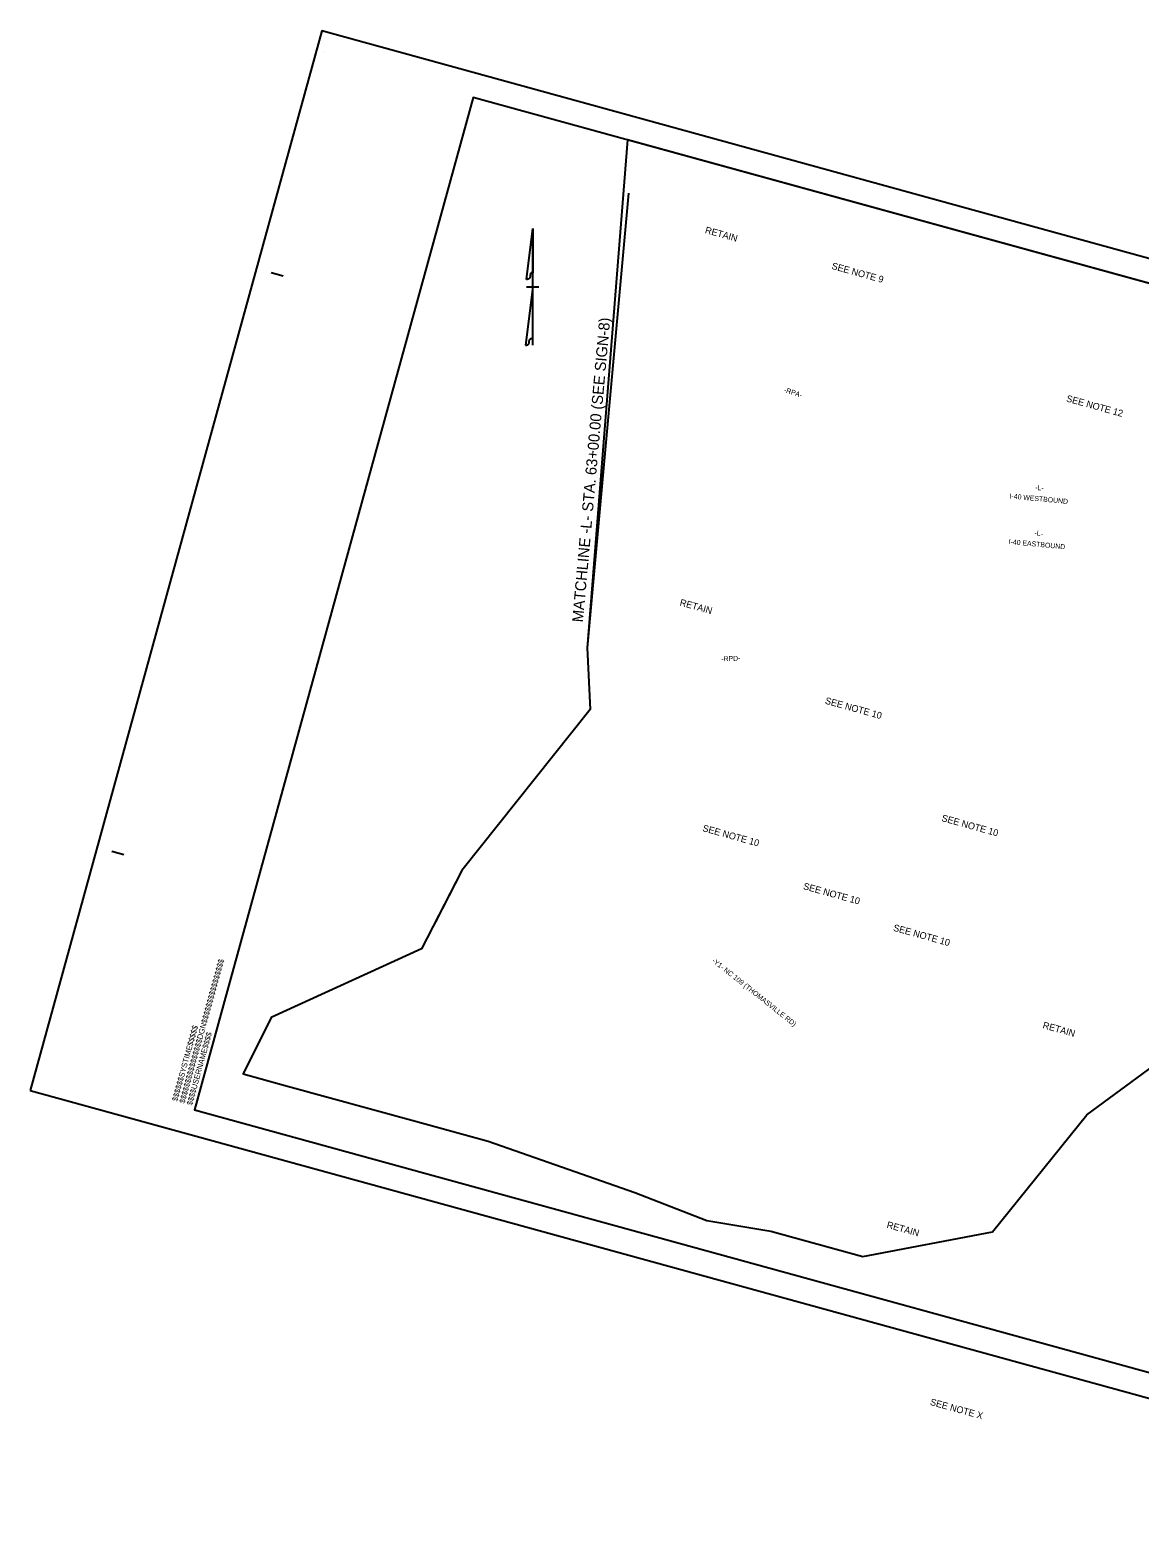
# Model space of a CAD drawing. Extents: x 1641195 to 1643343, y 841291 to 842800.
# Drawn here: x 1641195 to 1642306, y 841291 to 842800 of the extents above; entities that cross this region are included whole.
import ezdxf

# ---------------------------------------------------------------- set-up
doc = ezdxf.new("R2010")
doc.units = 0
for name, color, linetype in [('Default', 7, 'Continuous'), ('Level 14', 7, 'Continuous'), ('Level 15', 7, 'Continuous'), ('Level 17', 7, 'Continuous'), ('Level 2', 7, 'Continuous'), ('Level 3', 7, 'Continuous'), ('Level 5', 7, 'Continuous'), ('Level 6', 7, 'Continuous')]:
    doc.layers.add(name, color=color, linetype=linetype)

msp = doc.modelspace()

# ---------------------------------------------------------------- linework, layer by layer
at = {"layer": 'Level 14'}
msp.add_lwpolyline([(1641793.8, 842636.9), (1641752.4, 842181.8), (1641755.5, 842119.8), (1641627.2, 841958.8), (1641600.7, 841907.5)], dxfattribs=at)
at = {"layer": 'Level 15'}
for p, q in [((1641691.8, 842550.5), (1641698, 842601.5)), ((1641691.8, 842550.5), (1641698, 842601.5)), ((1641698, 842484.7), (1641698, 842601.5)), ((1641698, 842601.5), (1641698, 842557.2)), ((1641698, 842601.5), (1641698, 842557.2)), ((1641698, 842543.1), (1641690.8, 842484.7)), ((1641691.8, 842543.1), (1641704.3, 842543.1)), ((1641698, 842491.6), (1641698, 842543.1))]:
    msp.add_line(p, q, dxfattribs=at)
for points in [[(1641698, 842557.2), (1641695.5, 842557.5), (1641695.4, 842550.4), (1641691.8, 842550.5)], [(1641698, 842557.2), (1641695.5, 842557.5), (1641695.4, 842550.4), (1641691.8, 842550.5)], [(1641690.8, 842484.7), (1641694.5, 842484.5), (1641694.6, 842491.6), (1641698, 842491.6)]]:
    msp.add_open_spline(points, degree=2, dxfattribs=at)
at = {"layer": 'Level 2'}
msp.add_lwpolyline([(1641195.1, 841738.6), (1642822.6, 841290.7), (1643114.4, 842351.3), (1641486.9, 842799.2)], close=True, dxfattribs=at)
at = {"layer": 'Level 3'}
for p, q in [((1641488, 842800), (1641488, 842800)), ((1641489.6, 842777.7), (1641489.6, 842777.7)), ((1641639.4, 842732.4), (1641639.4, 842732.4)), ((1641436.2, 842557.3), (1641448.3, 842554)), ((1641276.9, 841978.2), (1641288.9, 841974.9)), ((1641359.5, 841719.2), (1641359.5, 841719.2)), ((1641359.5, 841719.2), (1641359.5, 841719.2)), ((1641359.5, 841719.2), (1641359.5, 841719.2)), ((1641359.5, 841719.2), (1641359.5, 841719.2)), ((1641359.5, 841719.2), (1641359.5, 841719.2)), ((1641359.5, 841719.2), (1641359.5, 841719.2)), ((1641359.5, 841719.2), (1641359.5, 841719.2)), ((1641359.5, 841719.2), (1641359.5, 841719.2))]:
    msp.add_line(p, q, dxfattribs=at)
msp.add_lwpolyline([(1643084, 842334.8), (1641638.4, 842732.6), (1641359.5, 841719.2), (1642805.1, 841321.4)], close=True, dxfattribs=at)
at = {"layer": 'Level 6'}
msp.add_lwpolyline([(1641793, 842690.1), (1641752.4, 842181.8), (1641755.5, 842119.8), (1641627.2, 841958.8), (1641586.6, 841880.3), (1641436.1, 841811.6), (1641408.4, 841755.1), (1641452.5, 841742.9), (1641576.9, 841708.7), (1641653.4, 841687.7), (1641800.3, 841636.5), (1641872.2, 841608.5), (1641936.5, 841597.7), (1642028.3, 841572.4), (1642158.2, 841597.2), (1642252.6, 841714.3), (1642387.3, 841813.3), (1642532.7, 841918.2), (1642817.6, 842071.9), (1642849.2, 842186.3), (1642903.7, 842384.5)], close=True, dxfattribs=at)

# ---------------------------------------------------------------- texts
at = {"layer": 'Default'}
for s, height, p in [('RETAIN', 6.77, (1641870, 842597)), ('SEE NOTE 9', 6.77, (1641996.7, 842561.1)), ('SEE NOTE 12', 6.771, (1642231.5, 842428.4)), ('RETAIN', 6.77, (1641844.7, 842224.2)), ('SEE NOTE 10', 6.771, (1641990.1, 842125.9)), ('SEE NOTE 10', 6.771, (1642106.7, 842008.4)), ('SEE NOTE 10', 6.771, (1641867.4, 841998.3)), ('SEE NOTE 10', 6.771, (1641968.2, 841940.2)), ('SEE NOTE 10', 6.771, (1642058.3, 841898.6)), ('RETAIN', 6.77, (1642207.9, 841801)), ('RETAIN', 6.77, (1642051.8, 841601.2)), ('SEE NOTE X', 6.77, (1642095.2, 841423.9))]:
    msp.add_text(s, height=height, rotation=344.4527, dxfattribs=at).set_placement(p)
at = {"layer": 'Level 17'}
msp.add_text('MATCHLINE -L- STA. 63+00.00 (SEE SIGN-8)', height=11, rotation=84.8642, dxfattribs=at).set_placement((1641748.3, 842206.9))
at = {"layer": 'Level 3'}
for s, p in [('$$$$$$$$$$$$$$$$DGN$$$$$$$$$$$$$$$$', (1641349.6, 841725.2)), ('$$$$$$SYSTIME$$$$$', (1641342.3, 841727.2)), ('$$$$USERNAME$$$$', (1641357, 841723.2))]:
    msp.add_text(s, height=5.581, rotation=74.6134, dxfattribs=at).set_placement(p)
at = {"layer": 'Level 5'}
for s, rotation, p in [('-RPA-', 341.6792, (1641949, 842437.9)), ('-L-', 354.6022, (1642200.9, 842339.8)), ('I-40 WESTBOUND', 354.6022, (1642175.1, 842331.2)), ('-L-', 354.6022, (1642200, 842294.2)), ('I-40 EASTBOUND', 354.6022, (1642174.2, 842285.6)), ('-RPD-', 2.2747, (1641886.8, 842168.1)), ('-Y1- NC 109 (THOMASVILLE RD)', 321.6338, (1641877, 841867.5))]:
    msp.add_text(s, height=5, rotation=rotation, dxfattribs=at).set_placement(p)

doc.saveas('drawing.dxf')
